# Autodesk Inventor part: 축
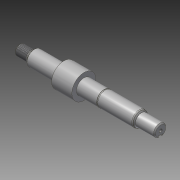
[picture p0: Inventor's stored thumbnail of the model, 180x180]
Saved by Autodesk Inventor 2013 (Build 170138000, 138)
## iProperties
Created: 2016-08
Part Number: 축
Material: 강철, 탄소
Document SubType Name: Modeling
Designer: mduedu
Density: 7.87 g/cm^3
Author: mduedu
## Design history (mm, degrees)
sketch "스케치1"
  geometry: L1 (-70, 0)-(70, 0); L2 (-70, 0)-(-70, 5); L3 (-70, 5)-(-56, 5); L4 (-56, 5)-(-56, 7.5); L5 (-56, 7.5)-(49.355, 7.5); L6 (51, 7.5)-(51, 6.55); L7 (51, 6)-(70, 6); L8 (70, 6)-(70, 0); L9 (51, 6.55)-(49.355, 7.5); L10 (49.355, 7.5)-(51, 7.5); L11 (51, 6.55)-(51, 6); 2 further points
  constraints: 22 end point, 7 parallel, 2 perpendicular, 1 coincident, 1 horizontal, 1 midpoint
  dimensions: "d0" = 140 distance of L1.start L1.end; "d2" = 14 distance of L2.end L3.end; "d3" = 19 distance of L7.start L7.end; "d4" = 10 diameter of L3 L1; "d5" = 15 diameter of L5 L1; "d6" = 12 diameter of L7 L1; "d63" = 13.1 diameter of L6.end L1; "d64" = 30 deg angle of L5 L9
revolve "회전1" sketch "스케치1" stored, may be unused: angle "d7" = 90 deg
sketch "스케치2"
  geometry: L1 (-56, -5)-(-56, 5) reference; L2 (70, -6)-(70, 6) reference; L3 (-56, 0)-(70, 0); L4 (-58, 4.5)-(-58, 5); L5 (-58, 5)-(-56, 5); L6 (-56, 5)-(-56, 4.5); L7 (-58, 4.5)-(-56, 4.5); 1 further point
  constraints: 10 end point, 2 midpoint, 1 parallel, 1 perpendicular, 1 point on line
  dimensions: "d8" = 2 distance of L4.end L5.end; "d10" = 10 diameter of L5 L3; "d11" = 9 diameter of L7 L3
revolve "회전2" sketch "스케치2" stored, may be unused: angle "d12" = 90 deg
node "작업 평면1"
sketch "스케치3"
  geometry: C1 r 12 at (0, 0); 1 further point
  constraints: 1 centre point, 1 coincident
  dimensions: "d15" = 24 diameter of C1
extrude "돌출1" join sketch "스케치3" distance "d16" = 20; taper "d17" = 0 deg
sketch "스케치5"
  geometry: L1 (-70, -5)-(-70, 5) reference; L2 (70, -6)-(70, 6) reference; L3 (-70, 0)-(70, 0); L4 (-6, 7.5)-(49.355, 7.5) reference; L5 (15.15, 7.5)-(14, 7.5); L6 (14, 7.5)-(14, 7.15); L7 (14, 7.15)-(15.15, 7.15); L8 (15.15, 7.15)-(15.15, 7.5); 1 further point
  constraints: 10 end point, 2 midpoint, 2 parallel, 1 horizontal, 1 perpendicular, 1 point on line
  dimensions: "d19" = 56 distance between parallel lines of L6 L2; "d20" = 1.15 distance between parallel lines of L8 L6; "d21" = 14.3 diameter of L7 L3
revolve "회전3" sketch "스케치5" stored, may be unused: angle "d22" = 90 deg
node "작업 평면3"
sketch "스케치6"
  geometry: L1 (6.5, 2)-(-9.5, 2); L2 (-9.5, 2)-(-9.5, -2); L3 (-9.5, -2)-(6.5, -2); L4 (-9.5, 6)-(-9.5, -6) reference; A1 r 2 centre (6.5, 0) between (6.5, -2) and (6.5, 2); 2 further points
  constraints: 6 end point, 2 midpoint, 2 point on circle, 2 tangent, 1 centre point, 1 horizontal, 1 horizontal alignment, 1 parallel, 1 perpendicular
  dimensions: "d23" = 4 distance between parallel lines of L3 L1; "d62" = 18 dimension on A1 L2
extrude "돌출2" cut sketch "스케치6" distance "d25" = 2.5; taper "d26" = 0 deg
feature "스레드1" dims "d27" = 10, "d28" = 0
fillet "모깎기1" dims "d65" = 2
fillet "모깎기2" dims "d66" = 0.5
chamfer "모따기5" distance "d41" = 0.5; stored, may be unused: second distance "d42" = 2, angle "d43" = 45 deg
chamfer "모따기7" distance "d47" = 1; stored, may be unused: second distance "d48" = 2, angle "d49" = 45 deg
chamfer "모따기8" distance "d50" = 1; stored, may be unused: second distance "d51" = 2, angle "d52" = 45 deg
sketch "스케치8"
  geometry: 1 further point
hole "구멍1" sketch "스케치8" at (2, 3.5) diameter "d53" = 3.242; stored, may be unused: countersink angle "d57" = 90 deg, drill point angle "d59" = 120 deg; dims "d54" = 10, "d55" = 4, "d56" = 2, "d58" = 12
node "솔리드1"
other parameters: "d13" = -44
